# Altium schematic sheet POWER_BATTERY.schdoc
size 127 x 101 mm
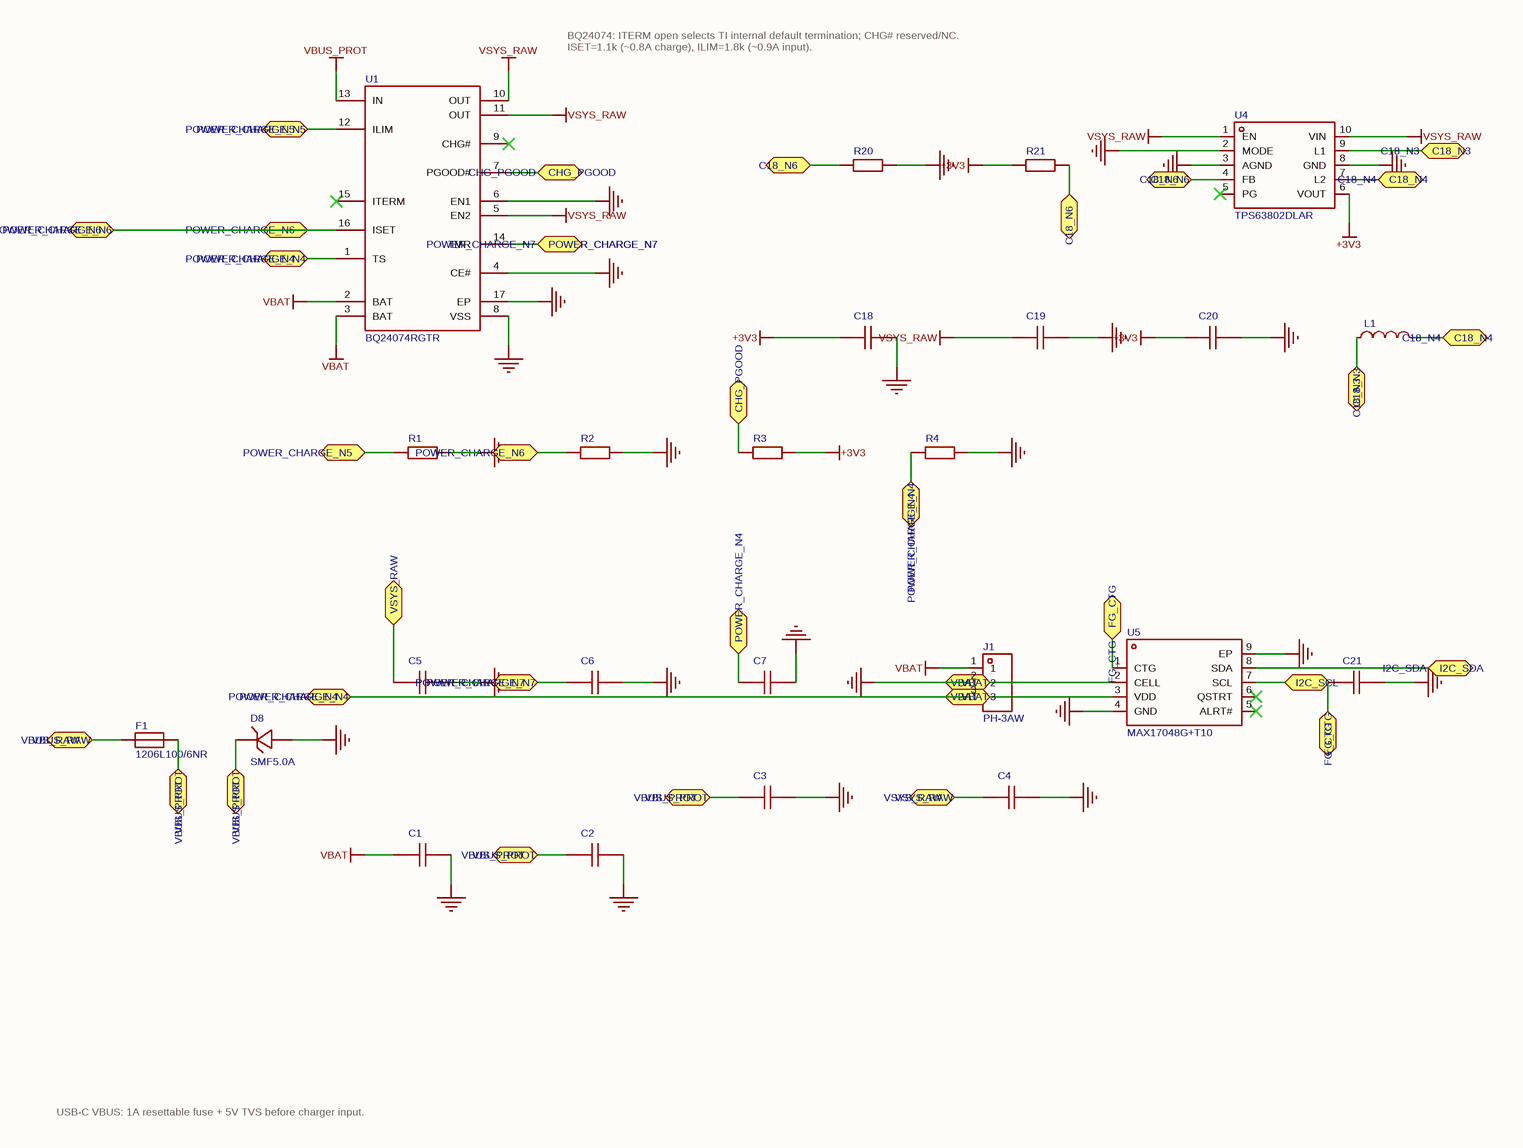
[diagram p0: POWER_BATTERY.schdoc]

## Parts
C1  (no value)  [C0805]
C2  (no value)  [C0402]
C3  (no value)  [C0805]
C4  (no value)  [C0805]
C5  (no value)  [C0402]
C6  (no value)  [C0402]
C7  (no value)  [C0402]
C18  (no value)  [C0402]
C19  (no value)  [C0805]
C20  (no value)  [C0805]
C21  (no value)  [C0402]
D8  SMF5.0A  [SOD-123FL_L2.8-W1.7-LS3.6-RD]
F1  1206L100/6NR  [F1206]
J1  PH-3AW  [CONN-TH_3P-P2.00_DEALON_PH-3AW_C2904959]
L1  (no value)  [IND-SMD_L5.0-W5.0_FNR50XXS]
R1  (no value)  [R0402]
R2  (no value)  [R0402]
R3  (no value)  [R0402]
R4  (no value)  [R0402]
R20  (no value)  [R0402]
R21  (no value)  [R0402]
U1  BQ24074RGTR  [QFN-16_L3.0-W3.0-P0.50-TL-EP1.7]
U4  TPS63802DLAR  [VSON-10_L3.0-W2.0-P0.50-TL]
U5  MAX17048G+T10  [TDFN-8_L2.0-W2.0-P0.50-BL-EP1.2]

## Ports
C18_N3 (bidir), C18_N4 (bidir), C18_N6 (bidir), CHG_PGOOD (bidir), FG_CTG (bidir), I2C_SCL (bidir), I2C_SDA (bidir), POWER_CHARGE_N4 (bidir), POWER_CHARGE_N5 (bidir), POWER_CHARGE_N6 (bidir), POWER_CHARGE_N7 (bidir), VBAT (bidir), VBUS_PROT (bidir), VBUS_RAW (bidir), VSYS_RAW (bidir)

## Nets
+3V3: C18.1 C20.1 R3.2 R21.1 U4.6(VOUT)
POWER_CHARGE_N4: C1.1 C1.2 C2.2 C3.2 C4.2 C5.2 C6.2 C7.1 C7.2 C18.2 C19.2 C20.2 C21.2 D8.2 J1.1 J1.2 J1.3 R1.2 R2.2 R4.1 R4.2 R20.2 U1.1(TS) U1.2(BAT) U1.3(BAT) U1.4(CE#) U1.6(EN1) U1.8(VSS) U1.17(EP) U4.2(MODE) U4.3(AGND) U4.8(GND) U5.2(CELL) U5.3(VDD) U5.4(GND) U5.9(EP) ; port POWER_CHARGE_N4, port VBAT  [also labelled GND, VBAT]
VBUS_PROT: C2.1 C3.1 D8.1 F1.2 U1.13(IN) ; port VBUS_PROT
VSYS_RAW: C4.1 C5.1 C19.1 U1.5(EN2) U1.10(OUT) U1.11(OUT) U4.1(EN) U4.10(VIN) ; port VSYS_RAW
C18_N3: L1.1 U4.9(L1) ; port C18_N3
C18_N4: L1.2 U4.7(L2) ; port C18_N4
C18_N6: R20.1 R21.2 U4.4(FB) ; port C18_N6
CHG_PGOOD: R3.1 U1.7(PGOOD#) ; port CHG_PGOOD
FG_CTG: C21.1 U5.1(CTG) ; port FG_CTG
I2C_SCL: U5.7(SCL) ; port I2C_SCL
I2C_SDA: U5.8(SDA) ; port I2C_SDA
POWER_CHARGE_N5: R1.1 U1.12(ILIM) ; port POWER_CHARGE_N5
POWER_CHARGE_N6: R2.1 U1.16(ISET) ; port POWER_CHARGE_N6
POWER_CHARGE_N7: C6.1 U1.14(TMR) ; port POWER_CHARGE_N7
VBUS_RAW: F1.1 ; port VBUS_RAW

Not connected (* = marked no-connect by the designer): U1 9(CHG#)* 15(ITERM)*; U4 5(PG)*; U5 5(ALRT#)* 6(QSTRT)*

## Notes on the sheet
- BQ24074: ITERM open selects TI internal default termination; CHG# reserved/NC.
  ISET=1.1k (~0.8A charge), ILIM=1.8k (~0.9A input).
- USB-C VBUS: 1A resettable fuse + 5V TVS before charger input.

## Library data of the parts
C1 C3 C4 C19 = GRM21BR61H106KE43L: Manufacturer: muRata(村田); Add into BOM: yes; ModelId: 1ba041120af144c991958decab20d2410819f05c4eef4c71ace90d822a990e87; ModelName: C0805_L2.0-W1.3-H1.3; ModelTransform: 78.74,51.181,0,0,0,0,0,0.0005,0
C2 = CL05A105KA5NQNC: Manufacturer: SAMSUNG(三星); Add into BOM: yes; ModelId: 36a51122f27c49738f86b3bfa98863e00819f05c4eef4c71ace90d822a990e87; ModelName: C0402_L1.0-W0.5-H0.5; ModelTransform: 39.37,19.685,0,0,0,0,0,0,0
C5-C7 C18 C21 = CL05B104KO5NNNC: Manufacturer: SAMSUNG(三星); Add into BOM: yes; ModelId: 36a51122f27c49738f86b3bfa98863e00819f05c4eef4c71ace90d822a990e87; ModelName: C0402_L1.0-W0.5-H0.5; ModelTransform: 39.37,19.685,0,0,0,0,0,0,0
C20 = CL21A226MAQNNNE: Manufacturer: SAMSUNG(三星); Add into BOM: yes; ModelId: 1ba041120af144c991958decab20d2410819f05c4eef4c71ace90d822a990e87; ModelName: C0805_L2.0-W1.3-H1.3; ModelTransform: 78.74,51.181,0,0,0,0,0,0.0005,0
D8 = SMF5.0A: Manufacturer: GOODWORK(固得沃克); Symbol: SMF5.0A_C2980403; Add into BOM: yes; ModelId: b9b923f0a64d4b9fb554884131211b980819f05c4eef4c71ace90d822a990e87; ModelTransform: 145.669,70.866,0,0,0,0,0,0,0
F1 = 1206L100/6NR: Manufacturer: LUTE(陆特); Add into BOM: yes; ModelId: f1628daad26847a79b887277a2bc85410819f05c4eef4c71ace90d822a990e87; ModelName: F1206_L3.2-W1.7-H0.6; ModelTransform: 125.984,66.929,0,0,0,0,0,0,0
J1 = PH-3AW: Manufacturer: DEALON(德艺隆); Symbol: PH-3AW_C2904959; Add into BOM: yes; ModelId: e20f212b0ed348e48f874ffd09aaaec70819f05c4eef4c71ace90d822a990e87; ModelTransform: 314.96,251.968,0,0,0,0,0,-113.937,-47.244
L1 = SWPA5040S1R0NT: Manufacturer: Sunlord(顺络); Add into BOM: yes; ModelId: 16215264b43040e7af8a95ab774880e30819f05c4eef4c71ace90d822a990e87; ModelName: IND-SMD_L5.0-W5.0-H2.0_FNR50XXS; ModelTransform: 196.85,196.85394,0,0,0,0,0,0,0
R1 = 0402WGF1801TCE: Manufacturer: UNI-ROYAL(厚声); Add into BOM: yes; ModelId: 98c88bc2b9094f218f3a3e30a70127380819f05c4eef4c71ace90d822a990e87; ModelName: R0402_L1.0-W0.5-H0.4; ModelTransform: 39.37,19.685,0,0,0,0,0,0,0
R2 = 0402WGF1101TCE: Manufacturer: UNI-ROYAL(厚声); Add into BOM: yes; ModelId: 98c88bc2b9094f218f3a3e30a70127380819f05c4eef4c71ace90d822a990e87; ModelName: R0402_L1.0-W0.5-H0.4; ModelTransform: 39.37,19.685,0,0,0,0,0,0,0
R3 = 0402WGF1003TCE: Manufacturer: UNI-ROYAL(厚声); Add into BOM: yes; ModelId: 98c88bc2b9094f218f3a3e30a70127380819f05c4eef4c71ace90d822a990e87; ModelName: R0402_L1.0-W0.5-H0.4; ModelTransform: 39.37,19.685,0,0,0,0,0,0,0
R4 = 0402WGF1002TCE: Manufacturer: UNI-ROYAL(厚声); Add into BOM: yes; ModelId: 98c88bc2b9094f218f3a3e30a70127380819f05c4eef4c71ace90d822a990e87; ModelName: R0402_L1.0-W0.5-H0.4; ModelTransform: 39.37,19.685,0,0,0,0,0,0,0
R20 = 0402WGF9102TCE: Manufacturer: UNI-ROYAL(厚声); Add into BOM: yes; ModelId: 98c88bc2b9094f218f3a3e30a70127380819f05c4eef4c71ace90d822a990e87; ModelName: R0402_L1.0-W0.5-H0.4; ModelTransform: 39.37,19.685,0,0,0,0,0,0,0
R21 = 0402WGF5113TCE: Manufacturer: UNI-ROYAL(厚声); Add into BOM: yes; ModelId: 98c88bc2b9094f218f3a3e30a70127380819f05c4eef4c71ace90d822a990e87; ModelName: R0402_L1.0-W0.5-H0.4; ModelTransform: 39.37,19.685,0,0,0,0,0,0,0
U1 = BQ24074RGTR: Manufacturer: TI(德州仪器); Add into BOM: yes; 3D Model: 4b11d3b5aea64910b85c54184b64922e0819f05c4eef4c71ace90d822a990e87; 3D Model Transform: 118.8974,118.8974,0,0,0,0,0,0,0; ModelName: QFN-16_L3.0-W3.0-P0.50-EP1.7
U4 = TPS63802DLAR_C2845237: Manufacturer: TI(德州仪器); Add into BOM: yes; ModelId: 8792291f24e34a10af08ce4e3a8467a60819f05c4eef4c71ace90d822a990e87; ModelTransform: 78.74,118.11,0,0,0,0,0,0,0
U5 = MAX17048G+T10: Manufacturer: ADI(亚德诺)/MAXIM(美信); Add into BOM: yes; 3D Model: 8ccff341f378482fb835cd62a8fe8c670819f05c4eef4c71ace90d822a990e87; 3D Model Transform: 78.74,79.527,0,0,0,0,0,0,0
